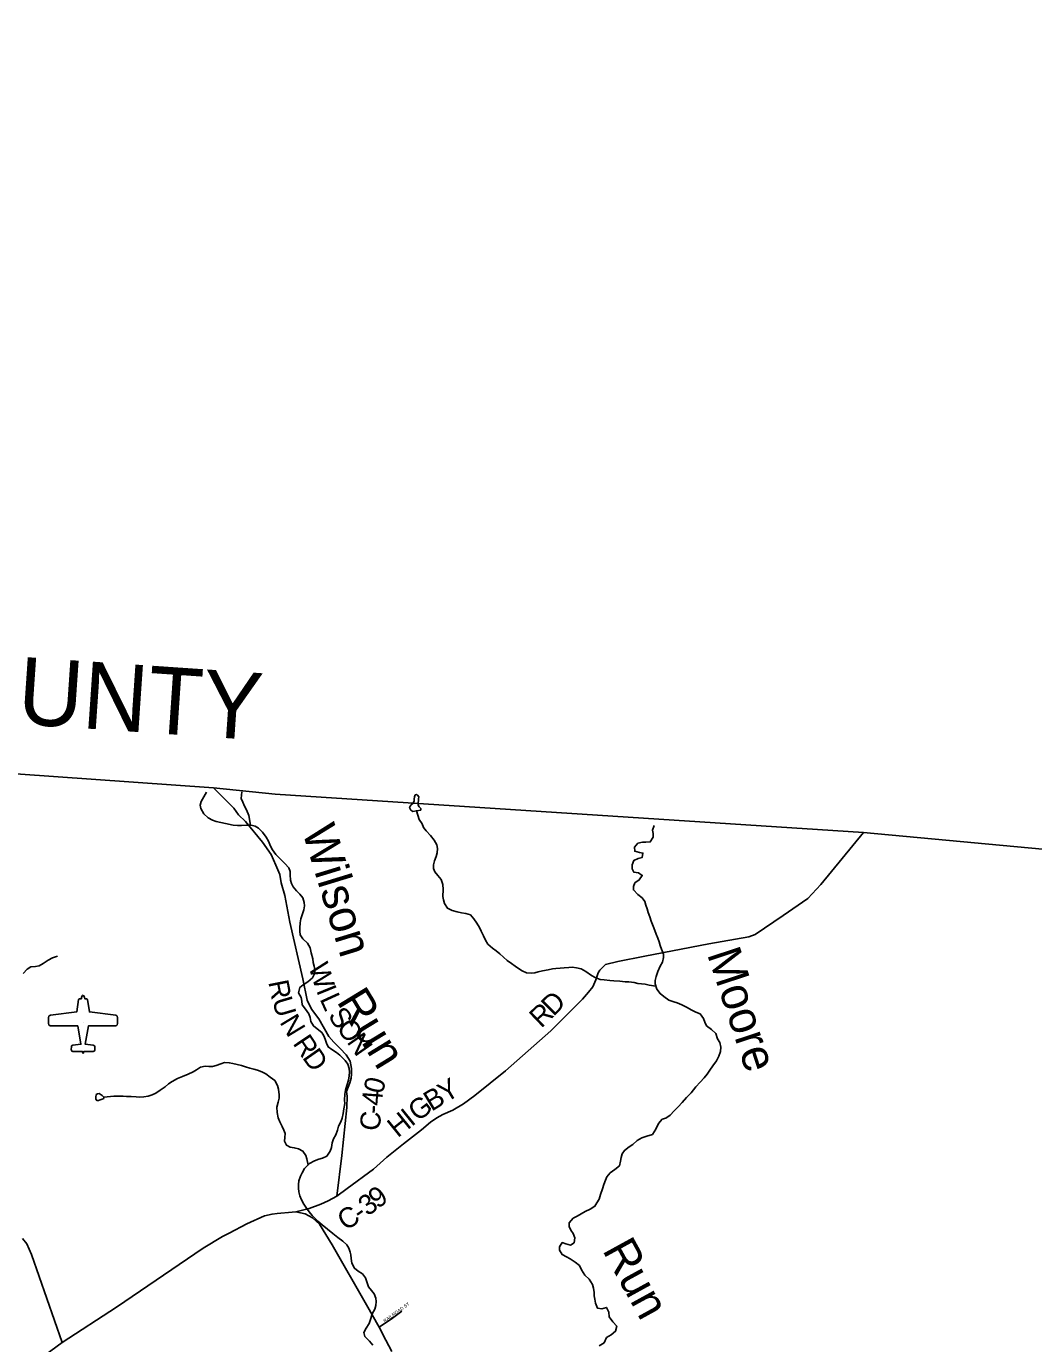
# Model space of a CAD drawing. Extents: x 1578669 to 1989827, y 208020 to 553079.
# Drawn here: x 1846418 to 1861421, y 420455 to 440074 of the extents above; entities that cross this region are included whole.
import ezdxf

# ---------------------------------------------------------------- set-up
doc = ezdxf.new("R2010")
doc.units = 0
for name, color, linetype in [('GM_X_Adjacent_County', 7, 'Continuous'), ('GM_X_Adjacent_County_Text', 7, 'Continuous'), ('GM_X_Airport_Class_3', 7, 'Continuous'), ('GM_X_Airport_Location_Class_3', 7, 'Continuous'), ('GM_X_County', 7, 'Continuous'), ('GM_X_County_Road', 7, 'Continuous'), ('GM_X_County_Road_Text', 7, 'Continuous'), ('GM_X_Minor_Lake', 7, 'Continuous'), ('GM_X_Minor_River', 7, 'Continuous'), ('GM_X_Minor_River_Text', 7, 'Continuous'), ('GM_X_State_Route', 7, 'Continuous'), ('GM_X_Township', 7, 'Continuous'), ('GM_X_Township_Subdivision', 7, 'Continuous'), ('GM_X_Township_Subdivision_Text', 7, 'Continuous')]:
    doc.layers.add(name, color=color, linetype=linetype)

msp = doc.modelspace()

# ---------------------------------------------------------------- linework, layer by layer
at = {"layer": 'GM_X_Adjacent_County'}
msp.add_lwpolyline([(1894201, 443179), (1894010, 440034), (1894011, 439989), (1893540, 433796), (1893501, 433286), (1892905, 425441), (1892420, 425479), (1887490, 425854), (1881971, 426273), (1874591, 426852), (1872750, 426991), (1872061, 427042), (1862193, 427760), (1858888, 428068), (1850126, 428641), (1849204, 428734), (1845065, 429025)], dxfattribs=at)
at = {"layer": 'GM_X_Airport_Class_3'}
for points in [[(1847263, 425644), (1847255, 425640), (1847247, 425628), (1847241, 425610), (1847238, 425592), (1847211, 425592), (1847201, 425588), (1847195, 425580), (1847169, 425396), (1846777, 425346), (1846760, 425339), (1846753, 425331), (1846748, 425313), (1846748, 425223), (1846754, 425203), (1846771, 425191), (1847184, 425188), (1847232, 424914), (1847110, 424900), (1847103, 424898), (1847092, 424889), (1847089, 424883), (1847088, 424832), (1847089, 424825), (1847098, 424812), (1847113, 424807), (1847250, 424807), (1847263, 424775)], [(1847263, 424775), (1847276, 424807), (1847413, 424807), (1847428, 424812), (1847437, 424825), (1847438, 424832), (1847437, 424883), (1847434, 424889), (1847423, 424898), (1847416, 424900), (1847295, 424914), (1847343, 425188), (1847756, 425191), (1847772, 425203), (1847778, 425223), (1847778, 425313), (1847773, 425331), (1847766, 425339), (1847749, 425346), (1847357, 425396), (1847331, 425580), (1847325, 425588), (1847315, 425592), (1847288, 425592), (1847285, 425610), (1847279, 425628), (1847271, 425640), (1847263, 425644)]]:
    msp.add_lwpolyline(points, dxfattribs=at)
at = {"layer": 'GM_X_Airport_Location_Class_3'}
msp.add_line((1847263, 425233), (1847263, 425233), dxfattribs=at)
at = {"layer": 'GM_X_County'}
msp.add_lwpolyline([(1845065, 429025), (1849204, 428734), (1850126, 428641), (1858888, 428068), (1862193, 427760), (1872061, 427042), (1872750, 426991), (1874591, 426852), (1881971, 426273), (1887490, 425854), (1886413, 413391), (1886177, 409905), (1886146, 409645), (1885513, 404405), (1885355, 401744), (1885146, 398934), (1884660, 393564)], dxfattribs=at)
at = {"layer": 'GM_X_County_Road'}
for points in [[(1851041, 422653), (1851118, 423259), (1851190, 423972), (1851197, 424139), (1851189, 424209), (1851211, 424277), (1851234, 424339), (1851254, 424407), (1851262, 424469), (1851261, 424553), (1851239, 424661), (1851182, 424756), (1851090, 424849), (1850997, 424943), (1850926, 425032), (1850775, 425295), (1850664, 425438), (1850600, 425571), (1850536, 425888), (1850343, 426733), (1850269, 427128), (1850214, 427319), (1850193, 427443), (1850136, 427584), (1850064, 427742), (1849934, 427923), (1849683, 428233), (1849578, 428330), (1849507, 428431), (1849415, 428523), (1849320, 428618), (1849204, 428734)], [(1850430, 422421), (1850632, 422467), (1850805, 422534), (1850915, 422581), (1851041, 422653), (1851198, 422764), (1851589, 423054), (1851790, 423234), (1852037, 423431), (1852304, 423640), (1852438, 423755), (1852531, 423819), (1852623, 423869), (1852769, 423934), (1852931, 424029), (1853098, 424149), (1853554, 424521), (1854231, 425114), (1854574, 425457), (1854701, 425587), (1854793, 425689), (1854856, 425771), (1854898, 425875), (1854935, 425977), (1854961, 426020), (1855045, 426102), (1855230, 426149), (1855628, 426225), (1856584, 426409), (1857181, 426514), (1857273, 426551), (1857692, 426834), (1858057, 427086), (1858251, 427292), (1858888, 428068)], [(1846360, 422022), (1846426, 421944), (1846497, 421781), (1846950, 420474)]]:
    msp.add_lwpolyline(points, dxfattribs=at)
at = {"layer": 'GM_X_Minor_Lake'}
for points in [[(1852171, 428494), (1852150, 428478), (1852136, 428462), (1852126, 428438), (1852144, 428402), (1852175, 428381), (1852229, 428391), (1852292, 428402), (1852292, 428426), (1852268, 428451), (1852252, 428475), (1852254, 428486)], [(1852254, 428486), (1852257, 428568), (1852262, 428600), (1852244, 428626), (1852228, 428634), (1852212, 428628), (1852202, 428598), (1852197, 428564), (1852195, 428536), (1852171, 428494)], [(1847570, 424128), (1847546, 424153), (1847520, 424171), (1847502, 424179), (1847478, 424175), (1847460, 424166), (1847454, 424126), (1847455, 424096), (1847467, 424079), (1847493, 424075), (1847517, 424085), (1847549, 424098)], [(1847549, 424098), (1847572, 424107), (1847572, 424112), (1847570, 424128)]]:
    msp.add_lwpolyline(points, dxfattribs=at)
at = {"layer": 'GM_X_Minor_River'}
for points in [[(1851174, 424231), (1851193, 424299), (1851216, 424379), (1851227, 424443), (1851229, 424499), (1851226, 424555), (1851209, 424617), (1851169, 424674), (1851088, 424753), (1851037, 424794), (1850969, 424837), (1850916, 424875), (1850890, 424930), (1850869, 424988), (1850850, 425040), (1850818, 425091), (1850749, 425144), (1850695, 425187), (1850656, 425255), (1850647, 425311), (1850627, 425368), (1850574, 425437), (1850525, 425501), (1850522, 425557), (1850510, 425610), (1850473, 425678), (1850492, 425760), (1850542, 425800), (1850609, 425843), (1850678, 425904), (1850717, 425974), (1850717, 426026), (1850706, 426078), (1850690, 426133), (1850685, 426189), (1850662, 426277), (1850645, 426350), (1850606, 426420), (1850537, 426485), (1850499, 426546), (1850492, 426598), (1850493, 426648), (1850497, 426724), (1850508, 426780), (1850527, 426844), (1850552, 426916), (1850559, 426976), (1850557, 427026), (1850538, 427093), (1850493, 427149), (1850441, 427198), (1850390, 427257), (1850366, 427307), (1850353, 427358), (1850350, 427436), (1850347, 427488), (1850327, 427540), (1850270, 427607), (1850199, 427676), (1850132, 427739), (1850086, 427808), (1850057, 427866), (1850026, 427937), (1849991, 428001), (1849936, 428074), (1849876, 428135), (1849825, 428162), (1849767, 428176), (1849699, 428177), (1849621, 428170), (1849563, 428171), (1849499, 428179), (1849387, 428201), (1849317, 428216), (1849245, 428234), (1849193, 428253), (1849124, 428286), (1849062, 428345), (1849015, 428425), (1849008, 428476), (1849023, 428528), (1849063, 428599), (1849102, 428669)], [(1849757, 428176), (1849732, 428323), (1849695, 428406), (1849670, 428460), (1849641, 428521), (1849619, 428575), (1849630, 428672)], [(1855794, 425780), (1855694, 425796), (1855637, 425807), (1855579, 425814), (1855527, 425820), (1855469, 425833), (1855393, 425842), (1855337, 425846), (1855257, 425853), (1855167, 425858), (1855111, 425863), (1855025, 425872), (1854963, 425881), (1854891, 425908), (1854834, 425940), (1854752, 425996), (1854681, 426036), (1854611, 426055), (1854547, 426060), (1854497, 426059), (1854427, 426055), (1854369, 426050), (1854307, 426045), (1854257, 426039), (1854189, 426024), (1854106, 426007), (1854044, 425992), (1853992, 425980), (1853936, 425973), (1853868, 425980), (1853804, 426009), (1853751, 426045), (1853699, 426078), (1853643, 426115), (1853580, 426161), (1853523, 426212), (1853471, 426259), (1853418, 426306), (1853362, 426346), (1853293, 426407), (1853255, 426464), (1853226, 426530), (1853195, 426599), (1853168, 426651), (1853128, 426720), (1853083, 426781), (1853032, 426843), (1852966, 426864), (1852902, 426873), (1852836, 426886), (1852763, 426905), (1852693, 426940), (1852648, 427010), (1852632, 427063), (1852623, 427115), (1852628, 427219), (1852621, 427295), (1852596, 427366), (1852545, 427428), (1852501, 427483), (1852482, 427533), (1852483, 427588), (1852499, 427646), (1852520, 427711), (1852535, 427763), (1852542, 427829), (1852532, 427884), (1852491, 427954), (1852438, 428025), (1852371, 428092), (1852335, 428145), (1852312, 428195), (1852271, 428264), (1852229, 428391)], [(1855517, 423481), (1855584, 423523), (1855662, 423544), (1855742, 423571), (1855795, 423648), (1855834, 423736), (1855889, 423800), (1855941, 423813), (1856006, 423858), (1856067, 423922), (1856125, 423983), (1856186, 424049), (1856253, 424122), (1856318, 424193), (1856391, 424279), (1856456, 424348), (1856513, 424416), (1856561, 424469), (1856600, 424527), (1856641, 424591), (1856696, 424668), (1856734, 424738), (1856755, 424804), (1856762, 424872), (1856747, 424942), (1856715, 424997), (1856690, 425073), (1856621, 425134), (1856550, 425189), (1856526, 425245), (1856503, 425300), (1856452, 425366), (1856392, 425391), (1856322, 425428), (1856263, 425461), (1856179, 425502), (1856111, 425529), (1856060, 425545), (1855990, 425570), (1855913, 425625), (1855857, 425668), (1855808, 425735), (1855783, 425815), (1855783, 425865), (1855798, 425923), (1855823, 425997), (1855860, 426079), (1855893, 426139), (1855909, 426207), (1855908, 426257), (1855879, 426333), (1855860, 426386), (1855842, 426438), (1855823, 426494), (1855800, 426555), (1855778, 426609), (1855753, 426674), (1855726, 426750), (1855705, 426812), (1855681, 426879), (1855664, 426929), (1855647, 426986), (1855631, 427042), (1855592, 427094), (1855525, 427147), (1855461, 427214), (1855460, 427264), (1855483, 427316), (1855547, 427362), (1855592, 427429), (1855534, 427468), (1855467, 427475), (1855441, 427529), (1855444, 427585), (1855465, 427653), (1855531, 427681), (1855593, 427698), (1855602, 427762), (1855550, 427771), (1855480, 427789), (1855475, 427852), (1855526, 427911), (1855594, 427922), (1855644, 427924), (1855712, 427927), (1855755, 428001), (1855752, 428053), (1855742, 428103), (1855767, 428173)], [(1846371, 425970), (1846429, 426033), (1846486, 426065), (1846556, 426074), (1846608, 426082), (1846670, 426115), (1846741, 426166), (1846808, 426201), (1846880, 426225)], [(1850614, 423116), (1850598, 423208), (1850581, 423260), (1850537, 423324), (1850472, 423359), (1850408, 423372), (1850346, 423381), (1850294, 423411), (1850261, 423470), (1850266, 423524), (1850274, 423584), (1850255, 423634), (1850228, 423687), (1850194, 423761), (1850169, 423820), (1850152, 423898), (1850151, 423976), (1850170, 424054), (1850182, 424110), (1850183, 424162), (1850174, 424247), (1850157, 424301), (1850118, 424374), (1850050, 424426), (1849985, 424475), (1849925, 424506), (1849861, 424529), (1849805, 424545), (1849746, 424560), (1849682, 424579), (1849622, 424596), (1849558, 424612), (1849494, 424627), (1849440, 424638), (1849372, 424641), (1849314, 424621), (1849246, 424596), (1849192, 424581), (1849138, 424581), (1849084, 424586), (1849011, 424571), (1848955, 424535), (1848903, 424504), (1848830, 424467), (1848744, 424433), (1848669, 424402), (1848591, 424359), (1848538, 424326), (1848486, 424282), (1848413, 424229), (1848347, 424186), (1848294, 424160), (1848232, 424139), (1848170, 424131), (1848110, 424128), (1848056, 424129), (1847978, 424134), (1847912, 424136), (1847858, 424139), (1847792, 424140), (1847720, 424139), (1847570, 424128)], [(1851577, 420431), (1851527, 420493), (1851462, 420564), (1851445, 420619), (1851479, 420688), (1851524, 420756), (1851551, 420832), (1851568, 420900), (1851611, 420971), (1851623, 421025), (1851628, 421083), (1851625, 421133), (1851601, 421198), (1851560, 421248), (1851515, 421303), (1851493, 421363), (1851468, 421434), (1851425, 421493), (1851361, 421537), (1851308, 421578), (1851266, 421653), (1851255, 421725), (1851250, 421777), (1851240, 421819), (1851223, 421876), (1851194, 421926), (1851132, 421981), (1851059, 422034), (1850985, 422095), (1850823, 422225), (1850761, 422280), (1850674, 422363), (1850629, 422418), (1850592, 422472), (1850552, 422535), (1850515, 422599), (1850494, 422656), (1850476, 422714), (1850471, 422772), (1850472, 422826), (1850478, 422878), (1850503, 422948), (1850526, 423000), (1850562, 423066), (1850635, 423137), (1850708, 423178), (1850776, 423205), (1850828, 423217), (1850893, 423248), (1850942, 423322), (1850962, 423378), (1850975, 423446), (1850994, 423508), (1851030, 423563), (1851055, 423633), (1851070, 423693), (1851101, 423757), (1851123, 423813), (1851138, 423885), (1851145, 423955), (1851160, 424033), (1851159, 424083), (1851162, 424169), (1851174, 424231)], [(1854950, 420422), (1855027, 420469), (1855061, 420545), (1855128, 420586), (1855193, 420639), (1855213, 420715), (1855154, 420782), (1855099, 420853), (1855094, 420925), (1855059, 420994), (1854990, 420974), (1854926, 420983), (1854895, 421058), (1854884, 421116), (1854878, 421166), (1854877, 421218), (1854866, 421282), (1854852, 421337), (1854801, 421415), (1854736, 421474), (1854687, 421555), (1854656, 421619), (1854594, 421670), (1854519, 421719), (1854463, 421746), (1854397, 421781), (1854358, 421847), (1854357, 421897), (1854401, 421961), (1854453, 421944), (1854523, 421924), (1854579, 421959), (1854590, 422029), (1854563, 422095), (1854530, 422146), (1854502, 422200), (1854501, 422257), (1854562, 422324), (1854624, 422355), (1854682, 422389), (1854743, 422426), (1854817, 422459), (1854888, 422501), (1854916, 422554), (1854949, 422608), (1854972, 422676), (1854999, 422762), (1855022, 422828), (1855042, 422890), (1855065, 422941), (1855114, 423001), (1855182, 423050), (1855251, 423106), (1855270, 423171), (1855280, 423229), (1855293, 423281), (1855326, 423333), (1855396, 423388), (1855451, 423420), (1855517, 423481)]]:
    msp.add_lwpolyline(points, dxfattribs=at)
at = {"layer": 'GM_X_State_Route'}
for points in [[(1850430, 422421), (1850379, 422416), (1850156, 422396), (1850078, 422386), (1849963, 422361), (1849703, 422242), (1849437, 422099), (1849339, 422051), (1849051, 421878), (1847761, 420998), (1846950, 420474), (1846616, 420225), (1846344, 420029)], [(1851863, 420339), (1851774, 420509), (1851675, 420700), (1851486, 421034), (1850971, 421927), (1850881, 422083), (1850783, 422236), (1850681, 422330), (1850572, 422388), (1850430, 422421)]]:
    msp.add_lwpolyline(points, dxfattribs=at)
at = {"layer": 'GM_X_Township'}
msp.add_lwpolyline([(1845065, 429025), (1849204, 428734), (1850126, 428641), (1858888, 428068), (1862193, 427760), (1872061, 427042), (1872750, 426991), (1874591, 426852), (1881971, 426273), (1887490, 425854), (1886413, 413391), (1886177, 409905), (1886146, 409645), (1885513, 404405), (1885355, 401744), (1885146, 398934), (1884660, 393564)], dxfattribs=at)
at = {"layer": 'GM_X_Township_Subdivision'}
msp.add_lwpolyline([(1851675, 420700), (1851798, 420784), (1851850, 420822), (1852012, 420940)], dxfattribs=at)

# ---------------------------------------------------------------- texts
at = {"layer": 'GM_X_Adjacent_County_Text'}
msp.add_text('ROSS COUNTY', height=1000, rotation=356.0927, dxfattribs=at).set_placement((1840116, 430108))
at = {"layer": 'GM_X_County_Road_Text'}
for s, rotation, p in [('W', 287.4498, (1850618, 426074)), ('R', 281.1071, (1850021, 425843)), ('I', 292.0958, (1850731, 425717)), ('U', 286.5268, (1850076, 425572)), ('L', 294.4985, (1850783, 425590)), ('D', 44.9778, (1854269, 425320)), ('N', 301.058, (1850184, 425244)), ('S', 304.0413, (1850903, 425339)), ('R', 43.6945, (1854086, 425145)), ('O', 307.1142, (1851026, 425157)), ('R', 303.7428, (1850379, 424928)), ('N', 304.9884, (1851184, 424948)), ('D', 305.0367, (1850520, 424717)), ('0', 76.0458, (1851725, 424163)), ('Y', 30.9713, (1852663, 424035)), ('4', 85.5514, (1851713, 423991)), ('B', 31.2516, (1852453, 423908)), ('-', 85.8682, (1851704, 423869)), ('G', 36.6739, (1852247, 423754)), ('C', 84.355, (1851679, 423615)), ('H', 38.9511, (1851949, 423513)), ('I', 38.867, (1852154, 423679)), ('9', 36.6774, (1851652, 422456)), ('3', 36.3885, (1851502, 422345)), ('C', 31.3848, (1851168, 422130)), ('-', 35.5751, (1851398, 422271))]:
    msp.add_text(s, height=300, rotation=rotation, dxfattribs=at).set_placement(p)
at = {"layer": 'GM_X_Minor_River_Text'}
for s, height, rotation, p in [('Wilson', 500.2, 287.0187, (1850521, 428098)), ('Moore', 500.1, 288.2887, (1856554, 426260)), ('Run', 500.1, 301.3898, (1851031, 425554)), ('Run', 500.1, 298.756, (1854991, 421850))]:
    msp.add_text(s, height=height, rotation=rotation, dxfattribs=at).set_placement(p)
at = {"layer": 'GM_X_Township_Subdivision_Text'}
msp.add_text('RAILROAD ST', height=50, rotation=35.6134, dxfattribs=at).set_placement((1851758, 420767))

doc.saveas('drawing.dxf')
